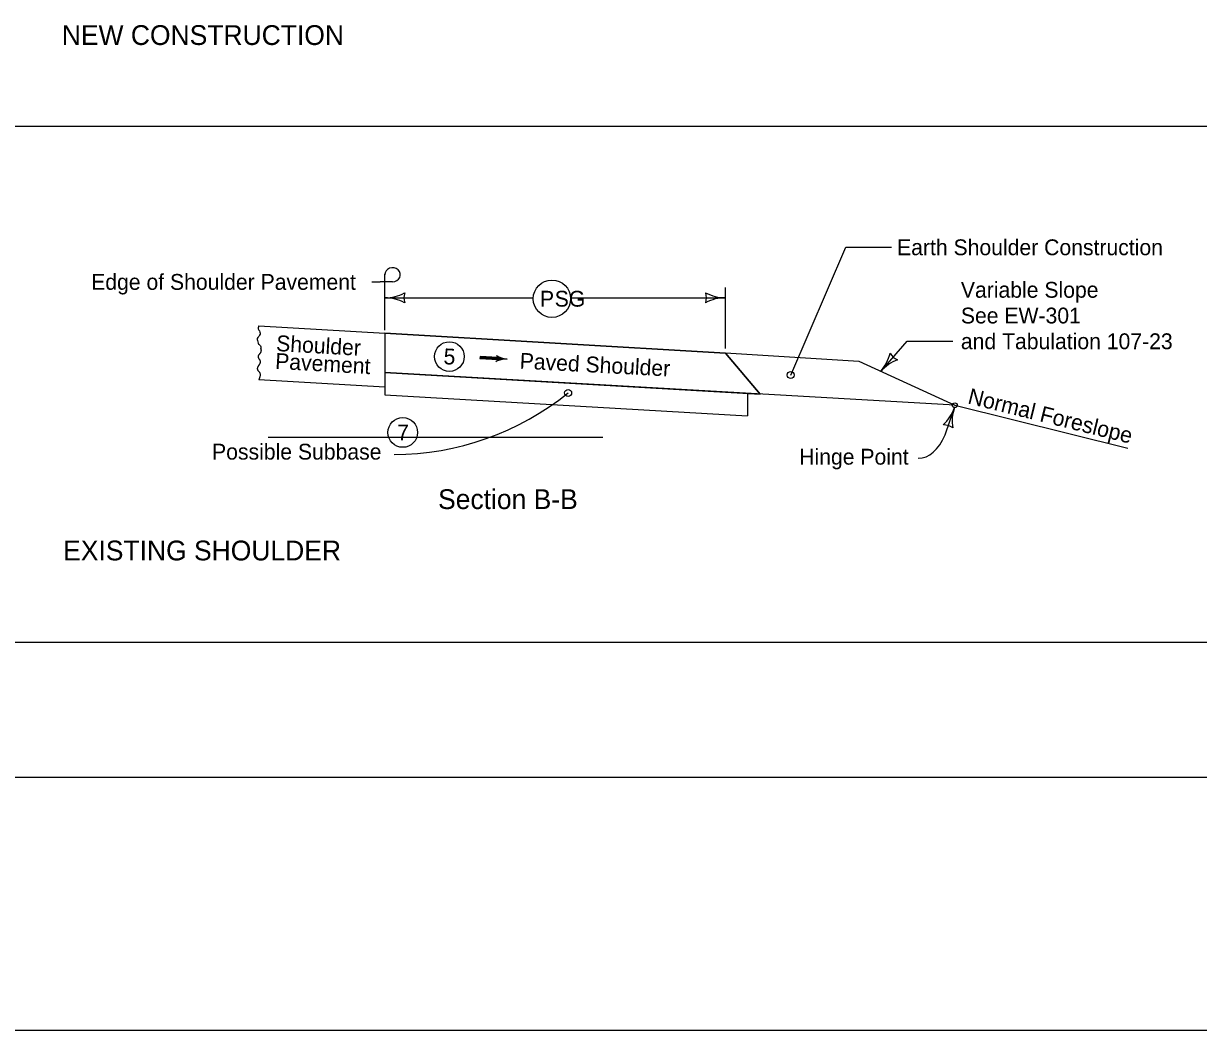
# Model space of a CAD drawing. Extents: x 10038 to 81668, y 7924 to 11018.
# Drawn here: x 11041 to 12229, y 7924 to 8942 of the extents above; entities that cross this region are included whole.
import ezdxf

# ---------------------------------------------------------------- set-up
doc = ezdxf.new("R2010")
doc.units = 0
for name, color, linetype in [('dsnCellElements', 7, 'Continuous'), ('DsnShtMinorGrid05', 7, 'Continuous'), ('DsnShtMinorGrid06', 7, 'Continuous'), ('DsnShtMinorGrid09', 7, 'Continuous'), ('DsnShtMinorGrid10', 7, 'Continuous'), ('DsnShtMinorGrid11', 7, 'Continuous'), ('DsnShtMinorGrid14', 7, 'Continuous'), ('Level 60', 7, 'Continuous'), ('SheetBorder', 7, 'Continuous')]:
    doc.layers.add(name, color=color, linetype=linetype)

msp = doc.modelspace()

# ---------------------------------------------------------------- linework, layer by layer
at = {"layer": 'dsnCellElements'}
msp.add_lwpolyline([(10037.7, 8180), (13358.6, 8180), (13358.6, 10373.4), (10037.7, 10373.4)], close=True, dxfattribs=at)
at = {"layer": 'DsnShtMinorGrid05'}
for p, q in [((11751.1, 8613.4), (11751.1, 8675.1)), ((11406.8, 8664.6), (11556.8, 8664.6)), ((11594.7, 8664.7), (11751.1, 8664.7))]:
    msp.add_line(p, q, dxfattribs=at)
msp.add_circle((11575.7, 8663.7), 18.9, dxfattribs=at)
for centre, radius, start, end in [((11406.8, 8707.1), 42.5, 270, 298.0725), ((11406.8, 8622.1), 42.5, 61.9275, 90), ((11442.5, 8664.6), 16.4, 162.2666, 197.7334), ((11715.5, 8664.7), 16.4, 342.2666, 17.7333), ((11751.1, 8707.2), 42.5, 241.9275, 270), ((11751.1, 8622.2), 42.5, 90, 118.0725), ((11415.4, 8788.3), 282, 270.132, 308.7946)]:
    msp.add_arc(centre, radius, start, end, dxfattribs=at)
at = {"layer": 'DsnShtMinorGrid06'}
msp.add_line((10150.3, 8316.7), (13246, 8316.7), dxfattribs=at)
at = {"layer": 'DsnShtMinorGrid09'}
for centre in [(11472, 8605.2), (11424.9, 8528.5)]:
    msp.add_circle(centre, 15, dxfattribs=at)
at = {"layer": 'DsnShtMinorGrid10'}
for p, q in [((11817.1, 8586.6), (11872.8, 8715.7)), ((11872.8, 8715.7), (11919.1, 8715.7)), ((11406.8, 8667.9), (11406.8, 8688.7)), ((11393.5, 8680.7), (11402.1, 8680.7)), ((11414.6, 8680.7), (11402.1, 8680.7)), ((11406.8, 8631.9), (11406.8, 8667.9)), ((11908.1, 8590.3), (11934.7, 8620.7)), ((11934.7, 8620.7), (11981, 8620.7)), ((11521.1, 8603.3), (11502.9, 8604.3)), ((11521, 8602.3), (11521, 8602.3)), ((11521.1, 8604.3), (11521.1, 8604.3)), ((11973.2, 8526.1), (11982.6, 8553.6))]:
    msp.add_line(p, q, dxfattribs=at)
for points in [[(11521.1, 8604.2), (11503, 8605.3), (11502.8, 8603.4), (11521, 8602.3), (11521.1, 8604), (11503.2, 8605.1), (11503.1, 8603.6), (11520.6, 8602.6), (11520.7, 8603.7), (11503.4, 8604.8), (11503.4, 8603.8), (11520.4, 8602.8), (11520.5, 8603.5), (11503.6, 8604.6), (11503.6, 8604), (11520.2, 8603.1)], [(11520.7, 8605.5), (11521.4, 8604.3), (11521.4, 8602.7), (11520.6, 8601.3), (11523.4, 8602.1), (11526.6, 8602.8), (11527.5, 8602.9), (11525.2, 8603.5), (11522, 8604.7), (11521.1, 8605.2), (11521.2, 8601.7), (11526.1, 8602.9), (11521.5, 8604.5), (11521.5, 8602.1), (11524.9, 8603), (11521.9, 8603.9), (11521.7, 8602.5), (11523.8, 8603), (11522.3, 8603.5), (11522.1, 8602.9), (11522.9, 8603)]]:
    msp.add_lwpolyline(points, dxfattribs=at)
for centre, radius, start, end in [((11876.1, 8618.3), 42.5, 318.8454, 346.9178), ((11940.1, 8562.3), 42.5, 110.7729, 138.8454), ((11931.5, 8617.1), 16.4, 211.112, 246.5787), ((11942.4, 8567.4), 42.5, 312.9788, 341.0513), ((12022.8, 8539.8), 42.5, 161.0513, 189.1238), ((11971.1, 8519.9), 16.4, 53.3179, 88.7846)]:
    msp.add_arc(centre, radius, start, end, dxfattribs=at)
for centre, major_axis, ratio, start_param, end_param in [((11414.6, 8687.9), (-7.81, 0), 0.913811, 1.570796, 6.283185), ((11517.3, 8603.5), (3.88, 0), 0.913811, 5.202895, 7.237436), ((11529.6, 8582.5), (22.2, 0), 0.913811, 1.537172, 2.061295), ((11532.4, 8622.9), (-22.2, 0), 0.913811, 0.954258, 1.478381), ((11946.1, 8563.9), (0, 61.5), 0.559383, 3.141593, 4.048985)]:
    msp.add_ellipse(centre, major_axis=major_axis, ratio=ratio, start_param=start_param, end_param=end_param, dxfattribs=at)
at = {"layer": 'DsnShtMinorGrid11'}
msp.add_line((12305.9, 8837.7), (10150.3, 8837.7), dxfattribs=at)
at = {"layer": 'DsnShtMinorGrid14'}
for centre in [(11817.1, 8586.6), (11592.1, 8568.5)]:
    msp.add_circle(centre, 3.54, dxfattribs=at)
at = {"layer": 'Level 60'}
for p, q in [((11279.4, 8636.2), (11406.8, 8628.8)), ((11406.8, 8628.8), (11406.8, 8574.8)), ((11406.8, 8628.8), (11751.1, 8608.8)), ((11751.1, 8608.8), (11406.8, 8628.8)), ((11406.8, 8628.8), (11406.8, 8589.2)), ((11750.7, 8609), (11750.7, 8609)), ((11751.1, 8608.9), (11885.9, 8600.5)), ((11751.1, 8608.8), (11786.2, 8567.3)), ((11786.2, 8567.3), (11751.1, 8608.8)), ((11885.9, 8600.5), (11982.9, 8556)), ((11982.9, 8556), (11406.8, 8589.2)), ((11406.8, 8589.2), (11786.2, 8567.3)), ((11279.4, 8582.2), (11406.8, 8574.8)), ((11773.4, 8582.5), (11773.4, 8582.5)), ((11406.8, 8574.8), (11406.8, 8566.4)), ((11406.8, 8566.4), (11773.4, 8545.2)), ((11773.4, 8568.1), (11773.4, 8545.2)), ((11982.9, 8556), (12157.9, 8512.7)), ((11288.8, 8523.9), (11627.3, 8523.9))]:
    msp.add_line(p, q, dxfattribs=at)
msp.add_circle((11472, 8605.2), 15, dxfattribs=at)
msp.add_ellipse((11982.9, 8556), major_axis=(2.58, 0), ratio=0.913811, dxfattribs=at)
for points in [[(11279.4, 8636.2), (11278.9, 8632.6), (11279.9, 8631.1), (11280.8, 8628.8), (11280.2, 8626.7), (11278.3, 8624.4), (11277.7, 8622.5), (11278.3, 8620.2), (11279.1, 8617.8), (11280.2, 8617.1), (11281.5, 8614.5), (11281.5, 8613.7)], [(11279.6, 8596.6), (11279.8, 8596.8), (11280, 8597.1), (11280.3, 8597.7), (11280.6, 8598.3), (11280.7, 8598.6), (11280.8, 8598.9), (11281, 8599.5), (11281, 8600.1), (11281, 8600.7), (11280.9, 8601), (11280.9, 8601.1), (11280.8, 8601.2), (11280.6, 8601.6), (11280.3, 8602), (11280, 8602.4), (11279.8, 8602.7), (11279.6, 8603), (11279.5, 8603.3), (11279.2, 8603.9), (11279, 8604.5), (11279, 8604.7), (11278.9, 8605), (11278.9, 8605.2), (11278.9, 8605.3), (11279.1, 8606.1), (11279.3, 8606.6), (11279.5, 8607.1), (11280, 8607.7), (11280.5, 8608.3), (11281, 8608.8), (11281.2, 8609.1), (11281.4, 8609.5), (11281.6, 8610), (11281.8, 8610.4), (11281.9, 8610.9), (11281.9, 8611.1), (11281.9, 8611.3), (11282, 8611.4), (11281.9, 8611.9), (11281.8, 8612.4), (11281.7, 8612.5), (11281.6, 8612.7), (11281.6, 8612.8), (11281.6, 8612.9), (11281.5, 8613.7)], [(11279.6, 8596.6), (11279.4, 8596.4), (11279.1, 8596.1), (11278.9, 8595.9), (11278.7, 8595.6), (11278.6, 8595.3), (11278.4, 8595), (11278.2, 8594.5), (11278, 8594.2), (11278, 8593.9), (11277.9, 8593.6), (11277.9, 8593.5), (11277.8, 8593.3), (11277.8, 8592.8), (11278, 8592.3), (11278.2, 8591.8), (11278.4, 8591.3), (11278.9, 8590.6), (11279.4, 8590.1), (11279.9, 8589.5), (11280.1, 8589.2), (11280.3, 8588.9), (11280.7, 8587.9), (11280.9, 8587.5), (11280.9, 8587), (11280.8, 8586.7), (11280.8, 8586.4), (11280.7, 8586.1), (11280.7, 8585.8), (11280.3, 8584.7), (11280.2, 8584.1), (11280, 8583.5), (11279.7, 8582.9), (11279.6, 8582.6), (11279.5, 8582.3), (11279.4, 8582.2)]]:
    msp.add_spline(points, degree=3, dxfattribs=at)
at = {"layer": 'SheetBorder'}
msp.add_lwpolyline([(10132.5, 9944), (13267.5, 9944), (13267.5, 7924), (10132.5, 7924)], close=True, dxfattribs=at)

# ---------------------------------------------------------------- texts
at = {"layer": 'DsnShtMinorGrid05'}
for s, p in [('P', (11563.6, 8655.7)), ('SG', (11578.5, 8655.7))]:
    msp.add_text(s, height=16, dxfattribs=at).set_placement(p)
at = {"layer": 'DsnShtMinorGrid09'}
msp.add_text('5', height=16, rotation=356.6997, dxfattribs=at).set_placement((11465.8, 8597.6))
msp.add_text('7', height=16, dxfattribs=at).set_placement((11419.2, 8520.5))
at = {"layer": 'DsnShtMinorGrid10'}
for s, height, p in [('NEW CONSTRUCTION', 20, (11080.2, 8920.2)), ('Earth Shoulder Construction', 16, (11924.6, 8707.7)), ('Edge of Shoulder Pavement', 16, (11109.9, 8672.7)), ('Variable Slope', 16, (11989.1, 8664.7)), ('See EW-301', 16, (11989.1, 8638.7)), ('and Tabulation 107-23', 16, (11989.1, 8612.7)), ('Possible Subbase', 16, (11232.1, 8501.1)), ('Hinge Point', 16, (11825.7, 8496)), ('Section B-B', 20, (11460.6, 8451.1)), ('EXISTING SHOULDER', 20, (11081.6, 8399.2))]:
    msp.add_text(s, height=height, dxfattribs=at).set_placement(p)
for s, rotation, p in [('Shoulder', 356.7346, (11296.6, 8610.9)), ('Pavement', 356.7346, (11295.6, 8592.9)), ('Paved Shoulder ', 356.983, (11542.8, 8593.1)), ('Normal Foreslope', 346.0988, (11995.2, 8558))]:
    msp.add_text(s, height=16, rotation=rotation, dxfattribs=at).set_placement(p)

doc.saveas('drawing.dxf')
